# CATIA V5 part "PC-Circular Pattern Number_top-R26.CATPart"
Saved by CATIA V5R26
Part number: Circular Pattern Number⇨ 3d-raku.com
Description:  COPYRIGHT 3Draku
Bounding box of the stored display mesh (mm): x -31 to 98.442, y -7.081 to 150, z -1 to 10
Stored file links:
  C:\Users\ina\OneDrive\03-etc\回転配置-No\PC-Circular Pattern Number_top-R26.CATPart
  C:\Users\ina\OneDrive\03-etc\回転配置-No\Circular Pattern Number_top.CATPart
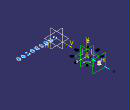
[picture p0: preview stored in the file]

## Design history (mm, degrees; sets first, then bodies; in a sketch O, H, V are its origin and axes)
Set1 "text"
  Sketch1 on xy-plane, origin (0, 0, 0), H (1, 0, 0), V (0, 1, 0)
    polyline C1
    polyline C2
    polyline C3
    polyline C4
    polyline C5
    polyline C6
    polyline C7
    polyline C8
    polyline C9
    polyline C10
    polyline C11
    polyline C12
    polyline C13
    polyline C14
    construction line L1 (-9.5916, 0) -> (108.8143, 0)
    construction line L2 (56.7358, 18.6315) -> (56.7358, 31.5447)
    construction line L3 (61.2271, 18.6315) -> (61.2271, 31.5447)
    point P7 (61.2271, 23.2349)
    construction line L4 (36.15, -12.9742) -> (36.15, 4.0786)
    construction line L5 (48.2, -12.9742) -> (48.2, 4.0786)
    construction line L6 (60.25, -12.9742) -> (60.25, 4.0786)
    construction line L7 (72.3, -12.9742) -> (72.3, 4.0786)
    construction line L8 (84.35, -12.9742) -> (84.35, 4.0786)
    construction line L9 (96.4, -12.9742) -> (96.4, 4.0786)
    construction line L10 (24.1, -12.9742) -> (24.1, 4.0786)
    construction line L11 (12.05, -12.9742) -> (12.05, 4.0786)
    construction line L12 (0, -12.9742) -> (0, 4.0786)
    construction line L13 (36.15, -12.9742) -> (48.2, -12.9742)
    construction line L14 (36.15, 4.0786) -> (48.2, 4.0786)
    construction line L15 (48.2, -12.9742) -> (60.25, -12.9742)
    construction line L16 (48.2, 4.0786) -> (60.25, 4.0786)
    construction line L17 (60.25, -12.9742) -> (72.3, -12.9742)
    construction line L18 (60.25, 4.0786) -> (72.3, 4.0786)
    construction line L19 (72.3, -12.9742) -> (84.35, -12.9742)
    construction line L20 (72.3, 4.0786) -> (84.35, 4.0786)
    construction line L21 (84.35, -12.9742) -> (96.4, -12.9742)
    construction line L22 (84.35, 4.0786) -> (96.4, 4.0786)
    construction line L23 (36.15, -12.9742) -> (24.1, -12.9742)
    construction line L24 (36.15, 4.0786) -> (24.1, 4.0786)
    construction line L25 (24.1, -12.9742) -> (12.05, -12.9742)
    construction line L26 (24.1, 4.0786) -> (12.05, 4.0786)
    construction line L27 (12.05, -12.9742) -> (0, -12.9742)
    construction line L28 (12.05, 4.0786) -> (0, 4.0786)
    point P26 (36.15, 0)
    point P27 (48.2, 0)
    point P28 (60.25, 0)
    point P29 (72.3, 0)
    point P30 (84.35, 0)
    point P31 (96.4, 0)
    point P32 (24.1, 0)
    point P33 (12.05, 0)
    point P34 (0, 0)
    distance L4 L5 = 12.05
    distance L5 L6 = 12.05
    distance L6 L7 = 12.05
    distance L7 L8 = 12.05
    distance L8 L9 = 12.05
    distance L4 L10 = 12.05
    distance L10 L11 = 12.05
    distance L11 L12 = 12.05
    horizontal: L1 H
    vertical: L2 V
    coincidence: L3 P7, L4 P26, L1 P26, L5 P27, L1 P27, L6 P28, L1 P28, L7 P29, L1 P29, L8 P30, L1 P30, L9 P31, L1 P31, L10 P32, L1 P32, L11 P33, L1 P33, L12 P34, L1 P34
    perpendicularity: L13 L4, L13 L5, L14 L4, L14 L5, L15 L5, L15 L6, L16 L5, L16 L6, L17 L6, L17 L7, L18 L6, L18 L7, L19 L7, L19 L8, L20 L7, L20 L8, L21 L8, L21 L9, L22 L8, L22 L9, L23 L4, L23 L10, L24 L4, L24 L10, L25 L10, L25 L11, L26 L10, L26 L11, L27 L11, L27 L12, L28 L11, L28 L12
Set2 "座標"
  Point1 "中心点": (0, 80, 0)
  AxisSystem1: origin (0, 80, 0), X (1, 0, 0), Y (0, 1, 0), Z (0, 0, 1)
  Plane1 "XY平面": type OffsetPt, RefPlane XY plane of AxisSystem1, RefPoint Point1
  Plane2 "YZ平面": type OffsetPt, RefPlane YZ plane of AxisSystem1, RefPoint Point1
  Plane3 "ZX平面": type OffsetPt, RefPlane ZX plane of AxisSystem1, RefPoint Point1
  Line1 "基準方向": type PtDir, RefPoint Point1, Direction edge [YZ plane of AxisSystem1 | XY plane of AxisSystem1], Start 0, End 10
  Line2 "中心軸": type PtDir, RefPoint Point1, Direction edge [ZX plane of AxisSystem1 | YZ plane of AxisSystem1], Start 0, End 10
  Sketch2 "profile curve" on Plane2, origin (0, 80, 0), H (0, 1, 0), V (0, 0, 1)
    line L1 (9.1716, 0) -> (70, 0)
    point P1 (70, 0)
    axis line L2 (0, 11.093) -> (0, -36.141)
    point P3 (0, 11.093)
    reference projected point E1 (0, 0) from Point1
    distance E1 P1 = 70
    angle L2 L1 = 90
    coincidence: O L1, P3 V
    vertical: L2 V
  Plane4 "position（ plane）": type Offset, RefPlane Plane3, Offset 32
Body1 (main body)
Body2
Body3 "Number"
  Body4 "No.1"
    Pad1: profile Scaling1, up to Offset1, opposite side length 1
    Set3
      Sketch3 on Plane5, origin (0, 111, 0), H (1, 0, 0), V (0, 1, 0)
        polyline C1
        construction polyline C2
        construction polyline C3
        construction polyline C4
        construction polyline C5
        construction polyline C6
        construction polyline C7
        construction polyline C8
        construction polyline C9
        construction polyline C10
        construction polyline C11
        construction polyline C12
        construction polyline C13
        construction polyline C14
        construction line L1 (-9.5916, 0) -> (108.8143, 0)
        construction line L2 (56.7358, 18.6315) -> (56.7358, 31.5447)
        construction line L3 (61.2271, 18.6315) -> (61.2271, 31.5447)
        point P7 (61.2271, 23.2349)
        construction line L4 (36.15, -12.9742) -> (36.15, 4.0786)
        construction line L5 (48.2, -12.9742) -> (48.2, 4.0786)
        construction line L6 (60.25, -12.9742) -> (60.25, 4.0786)
        construction line L7 (72.3, -12.9742) -> (72.3, 4.0786)
        construction line L8 (84.35, -12.9742) -> (84.35, 4.0786)
        construction line L9 (96.4, -12.9742) -> (96.4, 4.0786)
        construction line L10 (24.1, -12.9742) -> (24.1, 4.0786)
        construction line L11 (12.05, -12.9742) -> (12.05, 4.0786)
        construction line L12 (0, -12.9742) -> (0, 4.0786)
        construction line L13 (36.15, -12.9742) -> (48.2, -12.9742)
        construction line L14 (36.15, 4.0786) -> (48.2, 4.0786)
        construction line L15 (48.2, -12.9742) -> (60.25, -12.9742)
        construction line L16 (48.2, 4.0786) -> (60.25, 4.0786)
        construction line L17 (60.25, -12.9742) -> (72.3, -12.9742)
        construction line L18 (60.25, 4.0786) -> (72.3, 4.0786)
        construction line L19 (72.3, -12.9742) -> (84.35, -12.9742)
        construction line L20 (72.3, 4.0786) -> (84.35, 4.0786)
        construction line L21 (84.35, -12.9742) -> (96.4, -12.9742)
        construction line L22 (84.35, 4.0786) -> (96.4, 4.0786)
        construction line L23 (36.15, -12.9742) -> (24.1, -12.9742)
        construction line L24 (36.15, 4.0786) -> (24.1, 4.0786)
        construction line L25 (24.1, -12.9742) -> (12.05, -12.9742)
        construction line L26 (24.1, 4.0786) -> (12.05, 4.0786)
        construction line L27 (12.05, -12.9742) -> (0, -12.9742)
        construction line L28 (12.05, 4.0786) -> (0, 4.0786)
        point P26 (36.15, 0)
        point P27 (48.2, 0)
        point P28 (60.25, 0)
        point P29 (72.3, 0)
        point P30 (84.35, 0)
        point P31 (96.4, 0)
        point P32 (24.1, 0)
        point P33 (12.05, 0)
        point P34 (0, 0)
        distance L4 L5 = 12.05
        distance L5 L6 = 12.05
        distance L6 L7 = 12.05
        distance L7 L8 = 12.05
        distance L8 L9 = 12.05
        distance L4 L10 = 12.05
        distance L10 L11 = 12.05
        distance L11 L12 = 12.05
        horizontal: L1 H
        vertical: L2 V
        coincidence: L3 P7, L4 P26, L1 P26, L5 P27, L1 P27, L6 P28, L1 P28, L7 P29, L1 P29, L8 P30, L1 P30, L9 P31, L1 P31, L10 P32, L1 P32, L11 P33, L1 P33, L12 P34, L1 P34
        perpendicularity: L13 L4, L13 L5, L14 L4, L14 L5, L15 L5, L15 L6, L16 L5, L16 L6, L17 L6, L17 L7, L18 L6, L18 L7, L19 L7, L19 L8, L20 L7, L20 L8, L21 L8, L21 L9, L22 L8, L22 L9, L23 L4, L23 L10, L24 L4, L24 L10, L25 L10, L25 L11, L26 L10, L26 L11, L27 L11, L27 L12, L28 L11, L28 L12
      Scaling1: ToTransfor Sketch3, Reference Point2, Ratio 1
  Add1: tool Body4
  Body5 "No.2"
    Pad2: profile Scaling2, up to Offset1, opposite side length 1
    Rotate1: ToTransfor Pad2, Axis Line2, Angle 45
    Set4
      Sketch4 on Plane5, origin (0, 111, 0), H (1, 0, 0), V (0, 1, 0)
        construction polyline C1
        polyline C2
        construction polyline C3
        construction polyline C4
        construction polyline C5
        construction polyline C6
        construction polyline C7
        construction polyline C8
        construction polyline C9
        construction polyline C10
        construction polyline C11
        construction polyline C12
        construction polyline C13
        construction polyline C14
        construction line L1 (-21.6416, 0) -> (96.7643, 0)
        construction line L2 (56.7358, 18.6315) -> (56.7358, 31.5447)
        construction line L3 (61.2271, 18.6315) -> (61.2271, 31.5447)
        point P7 (61.2271, 23.2349)
        construction line L4 (24.1, -12.9742) -> (24.1, 4.0786)
        construction line L5 (36.15, -12.9742) -> (36.15, 4.0786)
        construction line L6 (48.2, -12.9742) -> (48.2, 4.0786)
        construction line L7 (60.25, -12.9742) -> (60.25, 4.0786)
        construction line L8 (72.3, -12.9742) -> (72.3, 4.0786)
        construction line L9 (84.35, -12.9742) -> (84.35, 4.0786)
        construction line L10 (12.05, -12.9742) -> (12.05, 4.0786)
        construction line L11 (0, -12.9742) -> (0, 4.0786)
        construction line L12 (-12.05, -12.9742) -> (-12.05, 4.0786)
        construction line L13 (24.1, -12.9742) -> (36.15, -12.9742)
        construction line L14 (24.1, 4.0786) -> (36.15, 4.0786)
        construction line L15 (36.15, -12.9742) -> (48.2, -12.9742)
        construction line L16 (36.15, 4.0786) -> (48.2, 4.0786)
        construction line L17 (48.2, -12.9742) -> (60.25, -12.9742)
        construction line L18 (48.2, 4.0786) -> (60.25, 4.0786)
        construction line L19 (60.25, -12.9742) -> (72.3, -12.9742)
        construction line L20 (60.25, 4.0786) -> (72.3, 4.0786)
        construction line L21 (72.3, -12.9742) -> (84.35, -12.9742)
        construction line L22 (72.3, 4.0786) -> (84.35, 4.0786)
        construction line L23 (24.1, -12.9742) -> (12.05, -12.9742)
        construction line L24 (24.1, 4.0786) -> (12.05, 4.0786)
        construction line L25 (12.05, -12.9742) -> (0, -12.9742)
        construction line L26 (12.05, 4.0786) -> (0, 4.0786)
        construction line L27 (0, -12.9742) -> (-12.05, -12.9742)
        construction line L28 (0, 4.0786) -> (-12.05, 4.0786)
        point P26 (24.1, 0)
        point P27 (36.15, 0)
        point P28 (48.2, 0)
        point P29 (60.25, 0)
        point P30 (72.3, 0)
        point P31 (84.35, 0)
        point P32 (12.05, 0)
        point P33 (0, 0)
        point P34 (-12.05, 0)
        distance L4 L5 = 12.05
        distance L5 L6 = 12.05
        distance L6 L7 = 12.05
        distance L7 L8 = 12.05
        distance L8 L9 = 12.05
        distance L4 L10 = 12.05
        distance L10 L11 = 12.05
        distance L11 L12 = 12.05
        horizontal: L1 H
        vertical: L2 V
        coincidence: L3 P7, L4 P26, L1 P26, L5 P27, L1 P27, L6 P28, L1 P28, L7 P29, L1 P29, L8 P30, L1 P30, L9 P31, L1 P31, L10 P32, L1 P32, L11 P33, L1 P33, L12 P34, L1 P34
        perpendicularity: L13 L4, L13 L5, L14 L4, L14 L5, L15 L5, L15 L6, L16 L5, L16 L6, L17 L6, L17 L7, L18 L6, L18 L7, L19 L7, L19 L8, L20 L7, L20 L8, L21 L8, L21 L9, L22 L8, L22 L9, L23 L4, L23 L10, L24 L4, L24 L10, L25 L10, L25 L11, L26 L10, L26 L11, L27 L11, L27 L12, L28 L11, L28 L12
      Scaling2: ToTransfor Sketch4, Reference Point2, Ratio 1 {= Scaling1.Ratio}
  Add2: tool Body5
  Body6 "No.3"
    Pad3: profile Scaling3, up to Offset1, opposite side length 1
    Rotate2: ToTransfor Pad3, Axis Line2, Angle 90 {= Rotate1.Angle *2}
    Set5
      Sketch5 on Plane5, origin (0, 111, 0), H (1, 0, 0), V (0, 1, 0)
        construction polyline C1
        construction polyline C2
        polyline C3
        construction polyline C4
        construction polyline C5
        construction polyline C6
        construction polyline C7
        construction polyline C8
        construction polyline C9
        construction polyline C10
        construction polyline C11
        construction polyline C12
        construction polyline C13
        construction polyline C14
        construction line L1 (-33.6916, 0) -> (84.7143, 0)
        construction line L2 (56.7358, 18.6315) -> (56.7358, 31.5447)
        construction line L3 (61.2271, 18.6315) -> (61.2271, 31.5447)
        point P7 (61.2271, 23.2349)
        construction line L4 (12.05, -12.9742) -> (12.05, 4.0786)
        construction line L5 (24.1, -12.9742) -> (24.1, 4.0786)
        construction line L6 (36.15, -12.9742) -> (36.15, 4.0786)
        construction line L7 (48.2, -12.9742) -> (48.2, 4.0786)
        construction line L8 (60.25, -12.9742) -> (60.25, 4.0786)
        construction line L9 (72.3, -12.9742) -> (72.3, 4.0786)
        construction line L10 (0, -12.9742) -> (0, 4.0786)
        construction line L11 (-12.05, -12.9742) -> (-12.05, 4.0786)
        construction line L12 (-24.1, -12.9742) -> (-24.1, 4.0786)
        construction line L13 (12.05, -12.9742) -> (24.1, -12.9742)
        construction line L14 (12.05, 4.0786) -> (24.1, 4.0786)
        construction line L15 (24.1, -12.9742) -> (36.15, -12.9742)
        construction line L16 (24.1, 4.0786) -> (36.15, 4.0786)
        construction line L17 (36.15, -12.9742) -> (48.2, -12.9742)
        construction line L18 (36.15, 4.0786) -> (48.2, 4.0786)
        construction line L19 (48.2, -12.9742) -> (60.25, -12.9742)
        construction line L20 (48.2, 4.0786) -> (60.25, 4.0786)
        construction line L21 (60.25, -12.9742) -> (72.3, -12.9742)
        construction line L22 (60.25, 4.0786) -> (72.3, 4.0786)
        construction line L23 (12.05, -12.9742) -> (0, -12.9742)
        construction line L24 (12.05, 4.0786) -> (0, 4.0786)
        construction line L25 (0, -12.9742) -> (-12.05, -12.9742)
        construction line L26 (0, 4.0786) -> (-12.05, 4.0786)
        construction line L27 (-12.05, -12.9742) -> (-24.1, -12.9742)
        construction line L28 (-12.05, 4.0786) -> (-24.1, 4.0786)
        point P26 (12.05, 0)
        point P27 (24.1, 0)
        point P28 (36.15, 0)
        point P29 (48.2, 0)
        point P30 (60.25, 0)
        point P31 (72.3, 0)
        point P32 (0, 0)
        point P33 (-12.05, 0)
        point P34 (-24.1, 0)
        distance L4 L5 = 12.05
        distance L5 L6 = 12.05
        distance L6 L7 = 12.05
        distance L7 L8 = 12.05
        distance L8 L9 = 12.05
        distance L4 L10 = 12.05
        distance L10 L11 = 12.05
        distance L11 L12 = 12.05
        horizontal: L1 H
        vertical: L2 V
        coincidence: L3 P7, L4 P26, L1 P26, L5 P27, L1 P27, L6 P28, L1 P28, L7 P29, L1 P29, L8 P30, L1 P30, L9 P31, L1 P31, L10 P32, L1 P32, L11 P33, L1 P33, L12 P34, L1 P34
        perpendicularity: L13 L4, L13 L5, L14 L4, L14 L5, L15 L5, L15 L6, L16 L5, L16 L6, L17 L6, L17 L7, L18 L6, L18 L7, L19 L7, L19 L8, L20 L7, L20 L8, L21 L8, L21 L9, L22 L8, L22 L9, L23 L4, L23 L10, L24 L4, L24 L10, L25 L10, L25 L11, L26 L10, L26 L11, L27 L11, L27 L12, L28 L11, L28 L12
      Scaling3: ToTransfor Sketch5, Reference Point2, Ratio 1 {= Scaling1.Ratio}
  Add3: tool Body6
  Body7 "No.4"
    Pad4: profile Scaling4, up to Offset1, opposite side length 1
    Rotate3: ToTransfor Pad4, Axis Line2, Angle 135 {= Rotate1.Angle *3}
    Set6
      Sketch6 on Plane5, origin (0, 111, 0), H (1, 0, 0), V (0, 1, 0)
        construction polyline C1
        construction polyline C2
        construction polyline C3
        polyline C4
        polyline C5
        construction polyline C6
        construction polyline C7
        construction polyline C8
        construction polyline C9
        construction polyline C10
        construction polyline C11
        construction polyline C12
        construction polyline C13
        construction polyline C14
        construction line L1 (-45.7416, 0) -> (72.6643, 0)
        construction line L2 (56.7358, 18.6315) -> (56.7358, 31.5447)
        construction line L3 (61.2271, 18.6315) -> (61.2271, 31.5447)
        point P7 (61.2271, 23.2349)
        construction line L4 (0, -12.9742) -> (0, 4.0786)
        construction line L5 (12.05, -12.9742) -> (12.05, 4.0786)
        construction line L6 (24.1, -12.9742) -> (24.1, 4.0786)
        construction line L7 (36.15, -12.9742) -> (36.15, 4.0786)
        construction line L8 (48.2, -12.9742) -> (48.2, 4.0786)
        construction line L9 (60.25, -12.9742) -> (60.25, 4.0786)
        construction line L10 (-12.05, -12.9742) -> (-12.05, 4.0786)
        construction line L11 (-24.1, -12.9742) -> (-24.1, 4.0786)
        construction line L12 (-36.15, -12.9742) -> (-36.15, 4.0786)
        construction line L13 (0, -12.9742) -> (12.05, -12.9742)
        construction line L14 (0, 4.0786) -> (12.05, 4.0786)
        construction line L15 (12.05, -12.9742) -> (24.1, -12.9742)
        construction line L16 (12.05, 4.0786) -> (24.1, 4.0786)
        construction line L17 (24.1, -12.9742) -> (36.15, -12.9742)
        construction line L18 (24.1, 4.0786) -> (36.15, 4.0786)
        construction line L19 (36.15, -12.9742) -> (48.2, -12.9742)
        construction line L20 (36.15, 4.0786) -> (48.2, 4.0786)
        construction line L21 (48.2, -12.9742) -> (60.25, -12.9742)
        construction line L22 (48.2, 4.0786) -> (60.25, 4.0786)
        construction line L23 (0, -12.9742) -> (-12.05, -12.9742)
        construction line L24 (0, 4.0786) -> (-12.05, 4.0786)
        construction line L25 (-12.05, -12.9742) -> (-24.1, -12.9742)
        construction line L26 (-12.05, 4.0786) -> (-24.1, 4.0786)
        construction line L27 (-24.1, -12.9742) -> (-36.15, -12.9742)
        construction line L28 (-24.1, 4.0786) -> (-36.15, 4.0786)
        point P26 (0, 0)
        point P27 (12.05, 0)
        point P28 (24.1, 0)
        point P29 (36.15, 0)
        point P30 (48.2, 0)
        point P31 (60.25, 0)
        point P32 (-12.05, 0)
        point P33 (-24.1, 0)
        point P34 (-36.15, 0)
        distance L4 L5 = 12.05
        distance L5 L6 = 12.05
        distance L6 L7 = 12.05
        distance L7 L8 = 12.05
        distance L8 L9 = 12.05
        distance L4 L10 = 12.05
        distance L10 L11 = 12.05
        distance L11 L12 = 12.05
        horizontal: L1 H
        vertical: L2 V
        coincidence: L3 P7, L4 P26, L1 P26, L5 P27, L1 P27, L6 P28, L1 P28, L7 P29, L1 P29, L8 P30, L1 P30, L9 P31, L1 P31, L10 P32, L1 P32, L11 P33, L1 P33, L12 P34, L1 P34
        perpendicularity: L13 L4, L13 L5, L14 L4, L14 L5, L15 L5, L15 L6, L16 L5, L16 L6, L17 L6, L17 L7, L18 L6, L18 L7, L19 L7, L19 L8, L20 L7, L20 L8, L21 L8, L21 L9, L22 L8, L22 L9, L23 L4, L23 L10, L24 L4, L24 L10, L25 L10, L25 L11, L26 L10, L26 L11, L27 L11, L27 L12, L28 L11, L28 L12
      Scaling4: ToTransfor Sketch6, Reference Point2, Ratio 1 {= Scaling1.Ratio}
  Add4: tool Body7
  Body8 "No.5"
    Pad5: profile Scaling5, up to Offset1, opposite side length 1
    Rotate4: ToTransfor Pad5, Axis Line2, Angle 180 {= Rotate1.Angle *4}
    Set7
      Sketch7 on Plane5, origin (0, 111, 0), H (1, 0, 0), V (0, 1, 0)
        construction polyline C1
        construction polyline C2
        construction polyline C3
        construction polyline C4
        construction polyline C5
        polyline C6
        construction polyline C7
        construction polyline C8
        construction polyline C9
        construction polyline C10
        construction polyline C11
        construction polyline C12
        construction polyline C13
        construction polyline C14
        construction line L1 (-57.7916, 0) -> (60.6143, 0)
        construction line L2 (56.7358, 18.6315) -> (56.7358, 31.5447)
        construction line L3 (61.2271, 18.6315) -> (61.2271, 31.5447)
        point P7 (61.2271, 23.2349)
        construction line L4 (-12.05, -12.9742) -> (-12.05, 4.0786)
        construction line L5 (0, -12.9742) -> (0, 4.0786)
        construction line L6 (12.05, -12.9742) -> (12.05, 4.0786)
        construction line L7 (24.1, -12.9742) -> (24.1, 4.0786)
        construction line L8 (36.15, -12.9742) -> (36.15, 4.0786)
        construction line L9 (48.2, -12.9742) -> (48.2, 4.0786)
        construction line L10 (-24.1, -12.9742) -> (-24.1, 4.0786)
        construction line L11 (-36.15, -12.9742) -> (-36.15, 4.0786)
        construction line L12 (-48.2, -12.9742) -> (-48.2, 4.0786)
        construction line L13 (-12.05, -12.9742) -> (0, -12.9742)
        construction line L14 (-12.05, 4.0786) -> (0, 4.0786)
        construction line L15 (0, -12.9742) -> (12.05, -12.9742)
        construction line L16 (0, 4.0786) -> (12.05, 4.0786)
        construction line L17 (12.05, -12.9742) -> (24.1, -12.9742)
        construction line L18 (12.05, 4.0786) -> (24.1, 4.0786)
        construction line L19 (24.1, -12.9742) -> (36.15, -12.9742)
        construction line L20 (24.1, 4.0786) -> (36.15, 4.0786)
        construction line L21 (36.15, -12.9742) -> (48.2, -12.9742)
        construction line L22 (36.15, 4.0786) -> (48.2, 4.0786)
        construction line L23 (-12.05, -12.9742) -> (-24.1, -12.9742)
        construction line L24 (-12.05, 4.0786) -> (-24.1, 4.0786)
        construction line L25 (-24.1, -12.9742) -> (-36.15, -12.9742)
        construction line L26 (-24.1, 4.0786) -> (-36.15, 4.0786)
        construction line L27 (-36.15, -12.9742) -> (-48.2, -12.9742)
        construction line L28 (-36.15, 4.0786) -> (-48.2, 4.0786)
        point P26 (-12.05, 0)
        point P27 (0, 0)
        point P28 (12.05, 0)
        point P29 (24.1, 0)
        point P30 (36.15, 0)
        point P31 (48.2, 0)
        point P32 (-24.1, 0)
        point P33 (-36.15, 0)
        point P34 (-48.2, 0)
        distance L4 L5 = 12.05
        distance L5 L6 = 12.05
        distance L6 L7 = 12.05
        distance L7 L8 = 12.05
        distance L8 L9 = 12.05
        distance L4 L10 = 12.05
        distance L10 L11 = 12.05
        distance L11 L12 = 12.05
        horizontal: L1 H
        vertical: L2 V
        coincidence: L3 P7, L4 P26, L1 P26, L5 P27, L1 P27, L6 P28, L1 P28, L7 P29, L1 P29, L8 P30, L1 P30, L9 P31, L1 P31, L10 P32, L1 P32, L11 P33, L1 P33, L12 P34, L1 P34
        perpendicularity: L13 L4, L13 L5, L14 L4, L14 L5, L15 L5, L15 L6, L16 L5, L16 L6, L17 L6, L17 L7, L18 L6, L18 L7, L19 L7, L19 L8, L20 L7, L20 L8, L21 L8, L21 L9, L22 L8, L22 L9, L23 L4, L23 L10, L24 L4, L24 L10, L25 L10, L25 L11, L26 L10, L26 L11, L27 L11, L27 L12, L28 L11, L28 L12
      Scaling5: ToTransfor Sketch7, Reference Point2, Ratio 1 {= Scaling1.Ratio}
  Add5: tool Body8
  Body9 "No.6"
    Pad6: profile Scaling6, up to Offset1, opposite side length 1
    Rotate5: ToTransfor Pad6, Axis Line2, Angle 225 {= Rotate1.Angle *5}
    Set8
      Sketch8 on Plane5, origin (0, 111, 0), H (1, 0, 0), V (0, 1, 0)
        construction polyline C1
        construction polyline C2
        construction polyline C3
        construction polyline C4
        construction polyline C5
        construction polyline C6
        polyline C7
        polyline C8
        construction polyline C9
        construction polyline C10
        construction polyline C11
        construction polyline C12
        construction polyline C13
        construction polyline C14
        construction line L1 (-69.8416, 0) -> (48.5643, 0)
        construction line L2 (56.7358, 18.6315) -> (56.7358, 31.5447)
        construction line L3 (61.2271, 18.6315) -> (61.2271, 31.5447)
        point P7 (61.2271, 23.2349)
        construction line L4 (-24.1, -12.9742) -> (-24.1, 4.0786)
        construction line L5 (-12.05, -12.9742) -> (-12.05, 4.0786)
        construction line L6 (0, -12.9742) -> (0, 4.0786)
        construction line L7 (12.05, -12.9742) -> (12.05, 4.0786)
        construction line L8 (24.1, -12.9742) -> (24.1, 4.0786)
        construction line L9 (36.15, -12.9742) -> (36.15, 4.0786)
        construction line L10 (-36.15, -12.9742) -> (-36.15, 4.0786)
        construction line L11 (-48.2, -12.9742) -> (-48.2, 4.0786)
        construction line L12 (-60.25, -12.9742) -> (-60.25, 4.0786)
        construction line L13 (-24.1, -12.9742) -> (-12.05, -12.9742)
        construction line L14 (-24.1, 4.0786) -> (-12.05, 4.0786)
        construction line L15 (-12.05, -12.9742) -> (0, -12.9742)
        construction line L16 (-12.05, 4.0786) -> (0, 4.0786)
        construction line L17 (0, -12.9742) -> (12.05, -12.9742)
        construction line L18 (0, 4.0786) -> (12.05, 4.0786)
        construction line L19 (12.05, -12.9742) -> (24.1, -12.9742)
        construction line L20 (12.05, 4.0786) -> (24.1, 4.0786)
        construction line L21 (24.1, -12.9742) -> (36.15, -12.9742)
        construction line L22 (24.1, 4.0786) -> (36.15, 4.0786)
        construction line L23 (-24.1, -12.9742) -> (-36.15, -12.9742)
        construction line L24 (-24.1, 4.0786) -> (-36.15, 4.0786)
        construction line L25 (-36.15, -12.9742) -> (-48.2, -12.9742)
        construction line L26 (-36.15, 4.0786) -> (-48.2, 4.0786)
        construction line L27 (-48.2, -12.9742) -> (-60.25, -12.9742)
        construction line L28 (-48.2, 4.0786) -> (-60.25, 4.0786)
        point P26 (-24.1, 0)
        point P27 (-12.05, 0)
        point P28 (0, 0)
        point P29 (12.05, 0)
        point P30 (24.1, 0)
        point P31 (36.15, 0)
        point P32 (-36.15, 0)
        point P33 (-48.2, 0)
        point P34 (-60.25, 0)
        distance L4 L5 = 12.05
        distance L5 L6 = 12.05
        distance L6 L7 = 12.05
        distance L7 L8 = 12.05
        distance L8 L9 = 12.05
        distance L4 L10 = 12.05
        distance L10 L11 = 12.05
        distance L11 L12 = 12.05
        horizontal: L1 H
        vertical: L2 V
        coincidence: L3 P7, L4 P26, L1 P26, L5 P27, L1 P27, L6 P28, L1 P28, L7 P29, L1 P29, L8 P30, L1 P30, L9 P31, L1 P31, L10 P32, L1 P32, L11 P33, L1 P33, L12 P34, L1 P34
        perpendicularity: L13 L4, L13 L5, L14 L4, L14 L5, L15 L5, L15 L6, L16 L5, L16 L6, L17 L6, L17 L7, L18 L6, L18 L7, L19 L7, L19 L8, L20 L7, L20 L8, L21 L8, L21 L9, L22 L8, L22 L9, L23 L4, L23 L10, L24 L4, L24 L10, L25 L10, L25 L11, L26 L10, L26 L11, L27 L11, L27 L12, L28 L11, L28 L12
      Scaling6: ToTransfor Sketch8, Reference Point2, Ratio 1 {= Scaling1.Ratio}
  Add6: tool Body9
  Body10 "No.7"
    Pad7: profile Scaling7, up to Offset1, opposite side length 1
    Rotate6: ToTransfor Pad7, Axis Line2, Angle 270 {= Rotate1.Angle *6}
    Set9
      Sketch9 on Plane5, origin (0, 111, 0), H (1, 0, 0), V (0, 1, 0)
        construction polyline C1
        construction polyline C2
        construction polyline C3
        construction polyline C4
        construction polyline C5
        construction polyline C6
        construction polyline C7
        construction polyline C8
        polyline C9
        construction polyline C10
        construction polyline C11
        construction polyline C12
        construction polyline C13
        construction polyline C14
        construction line L1 (-81.8916, 0) -> (36.5143, 0)
        construction line L2 (56.7358, 18.6315) -> (56.7358, 31.5447)
        construction line L3 (61.2271, 18.6315) -> (61.2271, 31.5447)
        point P7 (61.2271, 23.2349)
        construction line L4 (-36.15, -12.9742) -> (-36.15, 4.0786)
        construction line L5 (-24.1, -12.9742) -> (-24.1, 4.0786)
        construction line L6 (-12.05, -12.9742) -> (-12.05, 4.0786)
        construction line L7 (0, -12.9742) -> (0, 4.0786)
        construction line L8 (12.05, -12.9742) -> (12.05, 4.0786)
        construction line L9 (24.1, -12.9742) -> (24.1, 4.0786)
        construction line L10 (-48.2, -12.9742) -> (-48.2, 4.0786)
        construction line L11 (-60.25, -12.9742) -> (-60.25, 4.0786)
        construction line L12 (-72.3, -12.9742) -> (-72.3, 4.0786)
        construction line L13 (-36.15, -12.9742) -> (-24.1, -12.9742)
        construction line L14 (-36.15, 4.0786) -> (-24.1, 4.0786)
        construction line L15 (-24.1, -12.9742) -> (-12.05, -12.9742)
        construction line L16 (-24.1, 4.0786) -> (-12.05, 4.0786)
        construction line L17 (-12.05, -12.9742) -> (0, -12.9742)
        construction line L18 (-12.05, 4.0786) -> (0, 4.0786)
        construction line L19 (0, -12.9742) -> (12.05, -12.9742)
        construction line L20 (0, 4.0786) -> (12.05, 4.0786)
        construction line L21 (12.05, -12.9742) -> (24.1, -12.9742)
        construction line L22 (12.05, 4.0786) -> (24.1, 4.0786)
        construction line L23 (-36.15, -12.9742) -> (-48.2, -12.9742)
        construction line L24 (-36.15, 4.0786) -> (-48.2, 4.0786)
        construction line L25 (-48.2, -12.9742) -> (-60.25, -12.9742)
        construction line L26 (-48.2, 4.0786) -> (-60.25, 4.0786)
        construction line L27 (-60.25, -12.9742) -> (-72.3, -12.9742)
        construction line L28 (-60.25, 4.0786) -> (-72.3, 4.0786)
        point P26 (-36.15, 0)
        point P27 (-24.1, 0)
        point P28 (-12.05, 0)
        point P29 (0, 0)
        point P30 (12.05, 0)
        point P31 (24.1, 0)
        point P32 (-48.2, 0)
        point P33 (-60.25, 0)
        point P34 (-72.3, 0)
        distance L4 L5 = 12.05
        distance L5 L6 = 12.05
        distance L6 L7 = 12.05
        distance L7 L8 = 12.05
        distance L8 L9 = 12.05
        distance L4 L10 = 12.05
        distance L10 L11 = 12.05
        distance L11 L12 = 12.05
        horizontal: L1 H
        vertical: L2 V
        coincidence: L3 P7, L4 P26, L1 P26, L5 P27, L1 P27, L6 P28, L1 P28, L7 P29, L1 P29, L8 P30, L1 P30, L9 P31, L1 P31, L10 P32, L1 P32, L11 P33, L1 P33, L12 P34, L1 P34
        perpendicularity: L13 L4, L13 L5, L14 L4, L14 L5, L15 L5, L15 L6, L16 L5, L16 L6, L17 L6, L17 L7, L18 L6, L18 L7, L19 L7, L19 L8, L20 L7, L20 L8, L21 L8, L21 L9, L22 L8, L22 L9, L23 L4, L23 L10, L24 L4, L24 L10, L25 L10, L25 L11, L26 L10, L26 L11, L27 L11, L27 L12, L28 L11, L28 L12
      Scaling7: ToTransfor Sketch9, Reference Point2, Ratio 1 {= Scaling1.Ratio}
  Add7: tool Body10
  Body11 "No.8"
    Pad8: profile Scaling8, up to Offset1, opposite side length 1
    Rotate7: ToTransfor Pad8, Axis Line2, Angle 315 {= Rotate1.Angle *7}
    Set10
      Sketch10 on Plane5, origin (0, 111, 0), H (1, 0, 0), V (0, 1, 0)
        construction polyline C1
        construction polyline C2
        construction polyline C3
        construction polyline C4
        construction polyline C5
        construction polyline C6
        construction polyline C7
        construction polyline C8
        construction polyline C9
        polyline C10
        polyline C11
        polyline C12
        construction polyline C13
        construction polyline C14
        construction line L1 (-93.9416, 0) -> (24.4643, 0)
        construction line L2 (56.7358, 18.6315) -> (56.7358, 31.5447)
        construction line L3 (61.2271, 18.6315) -> (61.2271, 31.5447)
        point P7 (61.2271, 23.2349)
        construction line L4 (-48.2, -12.9742) -> (-48.2, 4.0786)
        construction line L5 (-36.15, -12.9742) -> (-36.15, 4.0786)
        construction line L6 (-24.1, -12.9742) -> (-24.1, 4.0786)
        construction line L7 (-12.05, -12.9742) -> (-12.05, 4.0786)
        construction line L8 (0, -12.9742) -> (0, 4.0786)
        construction line L9 (12.05, -12.9742) -> (12.05, 4.0786)
        construction line L10 (-60.25, -12.9742) -> (-60.25, 4.0786)
        construction line L11 (-72.3, -12.9742) -> (-72.3, 4.0786)
        construction line L12 (-84.35, -12.9742) -> (-84.35, 4.0786)
        construction line L13 (-48.2, -12.9742) -> (-36.15, -12.9742)
        construction line L14 (-48.2, 4.0786) -> (-36.15, 4.0786)
        construction line L15 (-36.15, -12.9742) -> (-24.1, -12.9742)
        construction line L16 (-36.15, 4.0786) -> (-24.1, 4.0786)
        construction line L17 (-24.1, -12.9742) -> (-12.05, -12.9742)
        construction line L18 (-24.1, 4.0786) -> (-12.05, 4.0786)
        construction line L19 (-12.05, -12.9742) -> (0, -12.9742)
        construction line L20 (-12.05, 4.0786) -> (0, 4.0786)
        construction line L21 (0, -12.9742) -> (12.05, -12.9742)
        construction line L22 (0, 4.0786) -> (12.05, 4.0786)
        construction line L23 (-48.2, -12.9742) -> (-60.25, -12.9742)
        construction line L24 (-48.2, 4.0786) -> (-60.25, 4.0786)
        construction line L25 (-60.25, -12.9742) -> (-72.3, -12.9742)
        construction line L26 (-60.25, 4.0786) -> (-72.3, 4.0786)
        construction line L27 (-72.3, -12.9742) -> (-84.35, -12.9742)
        construction line L28 (-72.3, 4.0786) -> (-84.35, 4.0786)
        point P26 (-48.2, 0)
        point P27 (-36.15, 0)
        point P28 (-24.1, 0)
        point P29 (-12.05, 0)
        point P30 (0, 0)
        point P31 (12.05, 0)
        point P32 (-60.25, 0)
        point P33 (-72.3, 0)
        point P34 (-84.35, 0)
        distance L4 L5 = 12.05
        distance L5 L6 = 12.05
        distance L6 L7 = 12.05
        distance L7 L8 = 12.05
        distance L8 L9 = 12.05
        distance L4 L10 = 12.05
        distance L10 L11 = 12.05
        distance L11 L12 = 12.05
        horizontal: L1 H
        vertical: L2 V
        coincidence: L3 P7, L4 P26, L1 P26, L5 P27, L1 P27, L6 P28, L1 P28, L7 P29, L1 P29, L8 P30, L1 P30, L9 P31, L1 P31, L10 P32, L1 P32, L11 P33, L1 P33, L12 P34, L1 P34
        perpendicularity: L13 L4, L13 L5, L14 L4, L14 L5, L15 L5, L15 L6, L16 L5, L16 L6, L17 L6, L17 L7, L18 L6, L18 L7, L19 L7, L19 L8, L20 L7, L20 L8, L21 L8, L21 L9, L22 L8, L22 L9, L23 L4, L23 L10, L24 L4, L24 L10, L25 L10, L25 L11, L26 L10, L26 L11, L27 L11, L27 L12, L28 L11, L28 L12
      Scaling8: ToTransfor Sketch10, Reference Point2, Ratio 1 {= Scaling1.Ratio}
  Add8: tool Body11
  Set11 "基準面"
    Revol1: Element1 Sketch2, Angle1 90
    Intersect1: ToIntersect1 Sketch2, ToIntersect2 Plane4
    Plane5: type Tangent, Support Revol1, RefPoint Intersect1
    Point2: type OnCurve, Support Sketch2, RefPoint Intersect1, Length 1
    Offset1: Offset Revol1, Length 1
Body12 "mark"
  Sketch11 on Plane5, origin (0, 112, 0), H (1, 0, 0), V (0, 1, 0)
    construction line L1 (0, -3.322) -> (0, 10.2065)
    point P3 (0, 3.4846)
    point P4 (0, 0)
    line L2 (0, 1) -> (0.75, 2.7)
    point P5 (0, 1)
    line L3 (0.75, 2.7) -> (-0.75, 2.7)
    line L4 (-0.75, 2.7) -> (0, 1)
    point P8 (0, 1)
    length L3 = 1.5
    distance P5 L3 = 1.7
    distance H P5 = 1
    vertical: L1 V
    coincidence: P3 L1, L1 P4, P5 L1, P8 L2, P8 L1, L1 V, P5 P8
    horizontal: L3 H
    symmetry: L2 L4 L1
  Pad9: profile Sketch11, direction (0, 0, -1), up to Offset1, opposite side length 1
